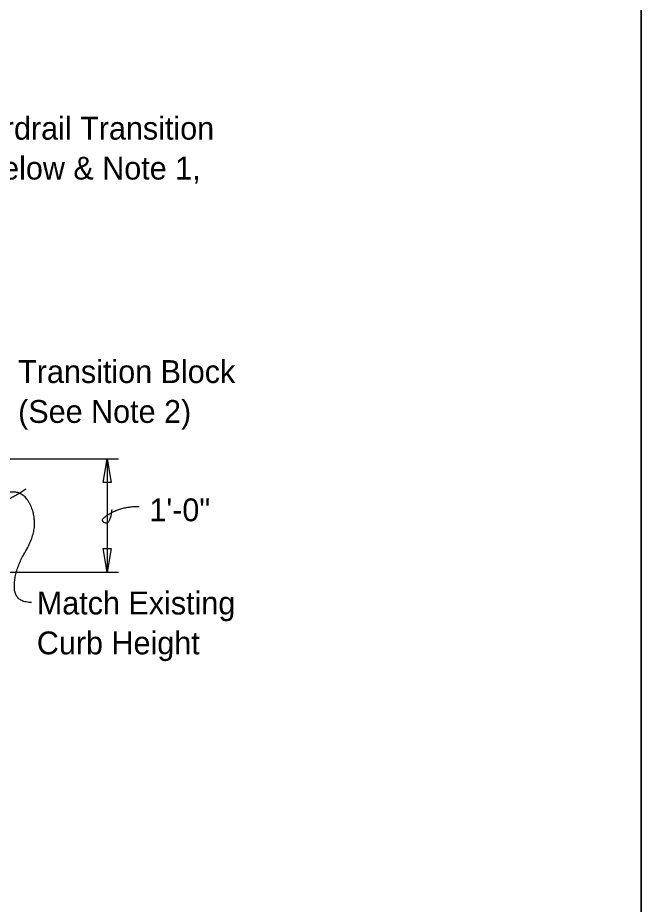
# Model space of a CAD drawing. Extents: x 0 to 41.1, y 0 to 26.
# Drawn here: x 35.56 to 41.07, y 7.83 to 15.65 of the extents above; entities that cross this region are included whole.
import ezdxf

# ---------------------------------------------------------------- set-up
doc = ezdxf.new("R2010")
doc.units = 0
for name, color, linetype in [('Dimension', 7, 'Continuous'), ('Miscellaneous1', 7, 'Continuous'), ('TextStructures', 7, 'Continuous')]:
    doc.layers.add(name, color=color, linetype=linetype)

# ---------------------------------------------------------------- blocks, each defined once
blk = doc.blocks.new('Terminator-Arrow')
at = {"layer": 'Dimension'}
blk.add_lwpolyline([(0, 0), (-0.00041, 0.000069), (-0.00041, -0.000069)], close=True, dxfattribs=at)

msp = doc.modelspace()

# ---------------------------------------------------------------- linework, layer by layer
at = {"layer": 'Dimension'}
for p, q in [((33.3449, 11.758), (36.4484, 11.758)), ((36.3487, 11.7581), (36.3487, 10.7581)), ((33.3449, 10.758), (36.4484, 10.758))]:
    msp.add_line(p, q, dxfattribs=at)
msp.add_lwpolyline([(0, 0), (41.0667, 0), (41.0667, 25.97), (0, 25.97)], close=True, dxfattribs=at)
for points in [[(35.6803, 10.4905), (35.5295, 10.4905), (35.5295, 10.7717), (35.7077, 11.0735), (35.7077, 11.293), (35.6049, 11.4645), (35.4335, 11.4645), (35.3582, 11.3822), (35.461, 11.3822), (35.6323, 11.492)], [(36.3902, 11.3106), (36.3742, 11.1692), (36.2728, 11.2212), (36.4902, 11.3385), (36.6315, 11.3385)]]:
    msp.add_open_spline(points, degree=2, dxfattribs=at)
at = {"layer": 'Miscellaneous1'}
msp.add_lwpolyline([(0, 25.97), (41.0667, 25.97), (41.0667, 0), (0, 0)], close=True, dxfattribs=at)

# ---------------------------------------------------------------- block references
at = {"layer": 'Dimension', "xscale": 506.349, "yscale": -512.1577380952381}
for p, rotation in [((36.3482, 11.7579), 90), ((36.3482, 10.7578), -90)]:
    msp.add_blockref('Terminator-Arrow', p, dxfattribs=dict(at, rotation=rotation))

# ---------------------------------------------------------------- texts
at = {"layer": 'Dimension'}
for s, p in [('Roadway Guardrail Transition', (33.7281, 14.5745)), ('(See Note 1 Below & Note 1,', (33.7281, 14.2225)), ('Transition Block', (35.5629, 12.427)), ('(See Note 2)', (35.5629, 12.075)), ('Match Existing ', (35.728, 10.3846)), ('Curb Height', (35.728, 10.0326))]:
    msp.add_text(s, height=0.2016, dxfattribs=at).set_placement(p)
at = {"layer": 'TextStructures'}
msp.add_text('1\'-0"', height=0.2016, dxfattribs=at).set_placement((36.7223, 11.2069))

doc.saveas('drawing.dxf')
